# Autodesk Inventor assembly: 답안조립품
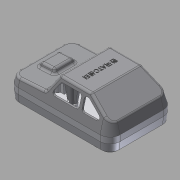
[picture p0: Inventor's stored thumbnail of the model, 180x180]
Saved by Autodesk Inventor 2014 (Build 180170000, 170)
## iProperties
Created: 2015-05
Part Number: 답안조립품
Document SubType Name: Assembly
Designer: Administrator
Author: Administrator
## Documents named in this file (7)
- C:\Documents and Settings\Administrator\바탕 화면\450508V1022\답안조립품.iam
- C:\Documents and Settings\Administrator\바탕 화면\450508V1022\본체.ipt
- C:\Documents and Settings\Administrator\바탕 화면\450508V1022\커버.ipt
- C:\Documents and Settings\Administrator\바탕 화면\450508V1022\바퀴고정부.ipt
- C:\Documents and Settings\Administrator\바탕 화면\450508V1022\M4x10.ipt
- C:\Documents and Settings\Administrator\바탕 화면\450508V1022\M2x4.ipt
- C:\Documents and Settings\Administrator\바탕 화면\450508V1022\바퀴.ipt
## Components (20 placed, 2 different names)
1. M4x10:1
2. M4x10:2
3. M4x10:3
4. M4x10:4
5. M2x4:1
6. M2x4:2
7. M2x4:3
8. M2x4:4
9. M2x4:5
10. M2x4:6
11. M2x4:7
12. M2x4:8
13. M2x4:9
14. M2x4:10
15. M2x4:11
16. M2x4:12
17. M2x4:13
18. M2x4:14
19. M2x4:15
20. M2x4:16
